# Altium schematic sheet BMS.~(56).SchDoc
size A3; SheetNumber: 8; SheetTotal: 14
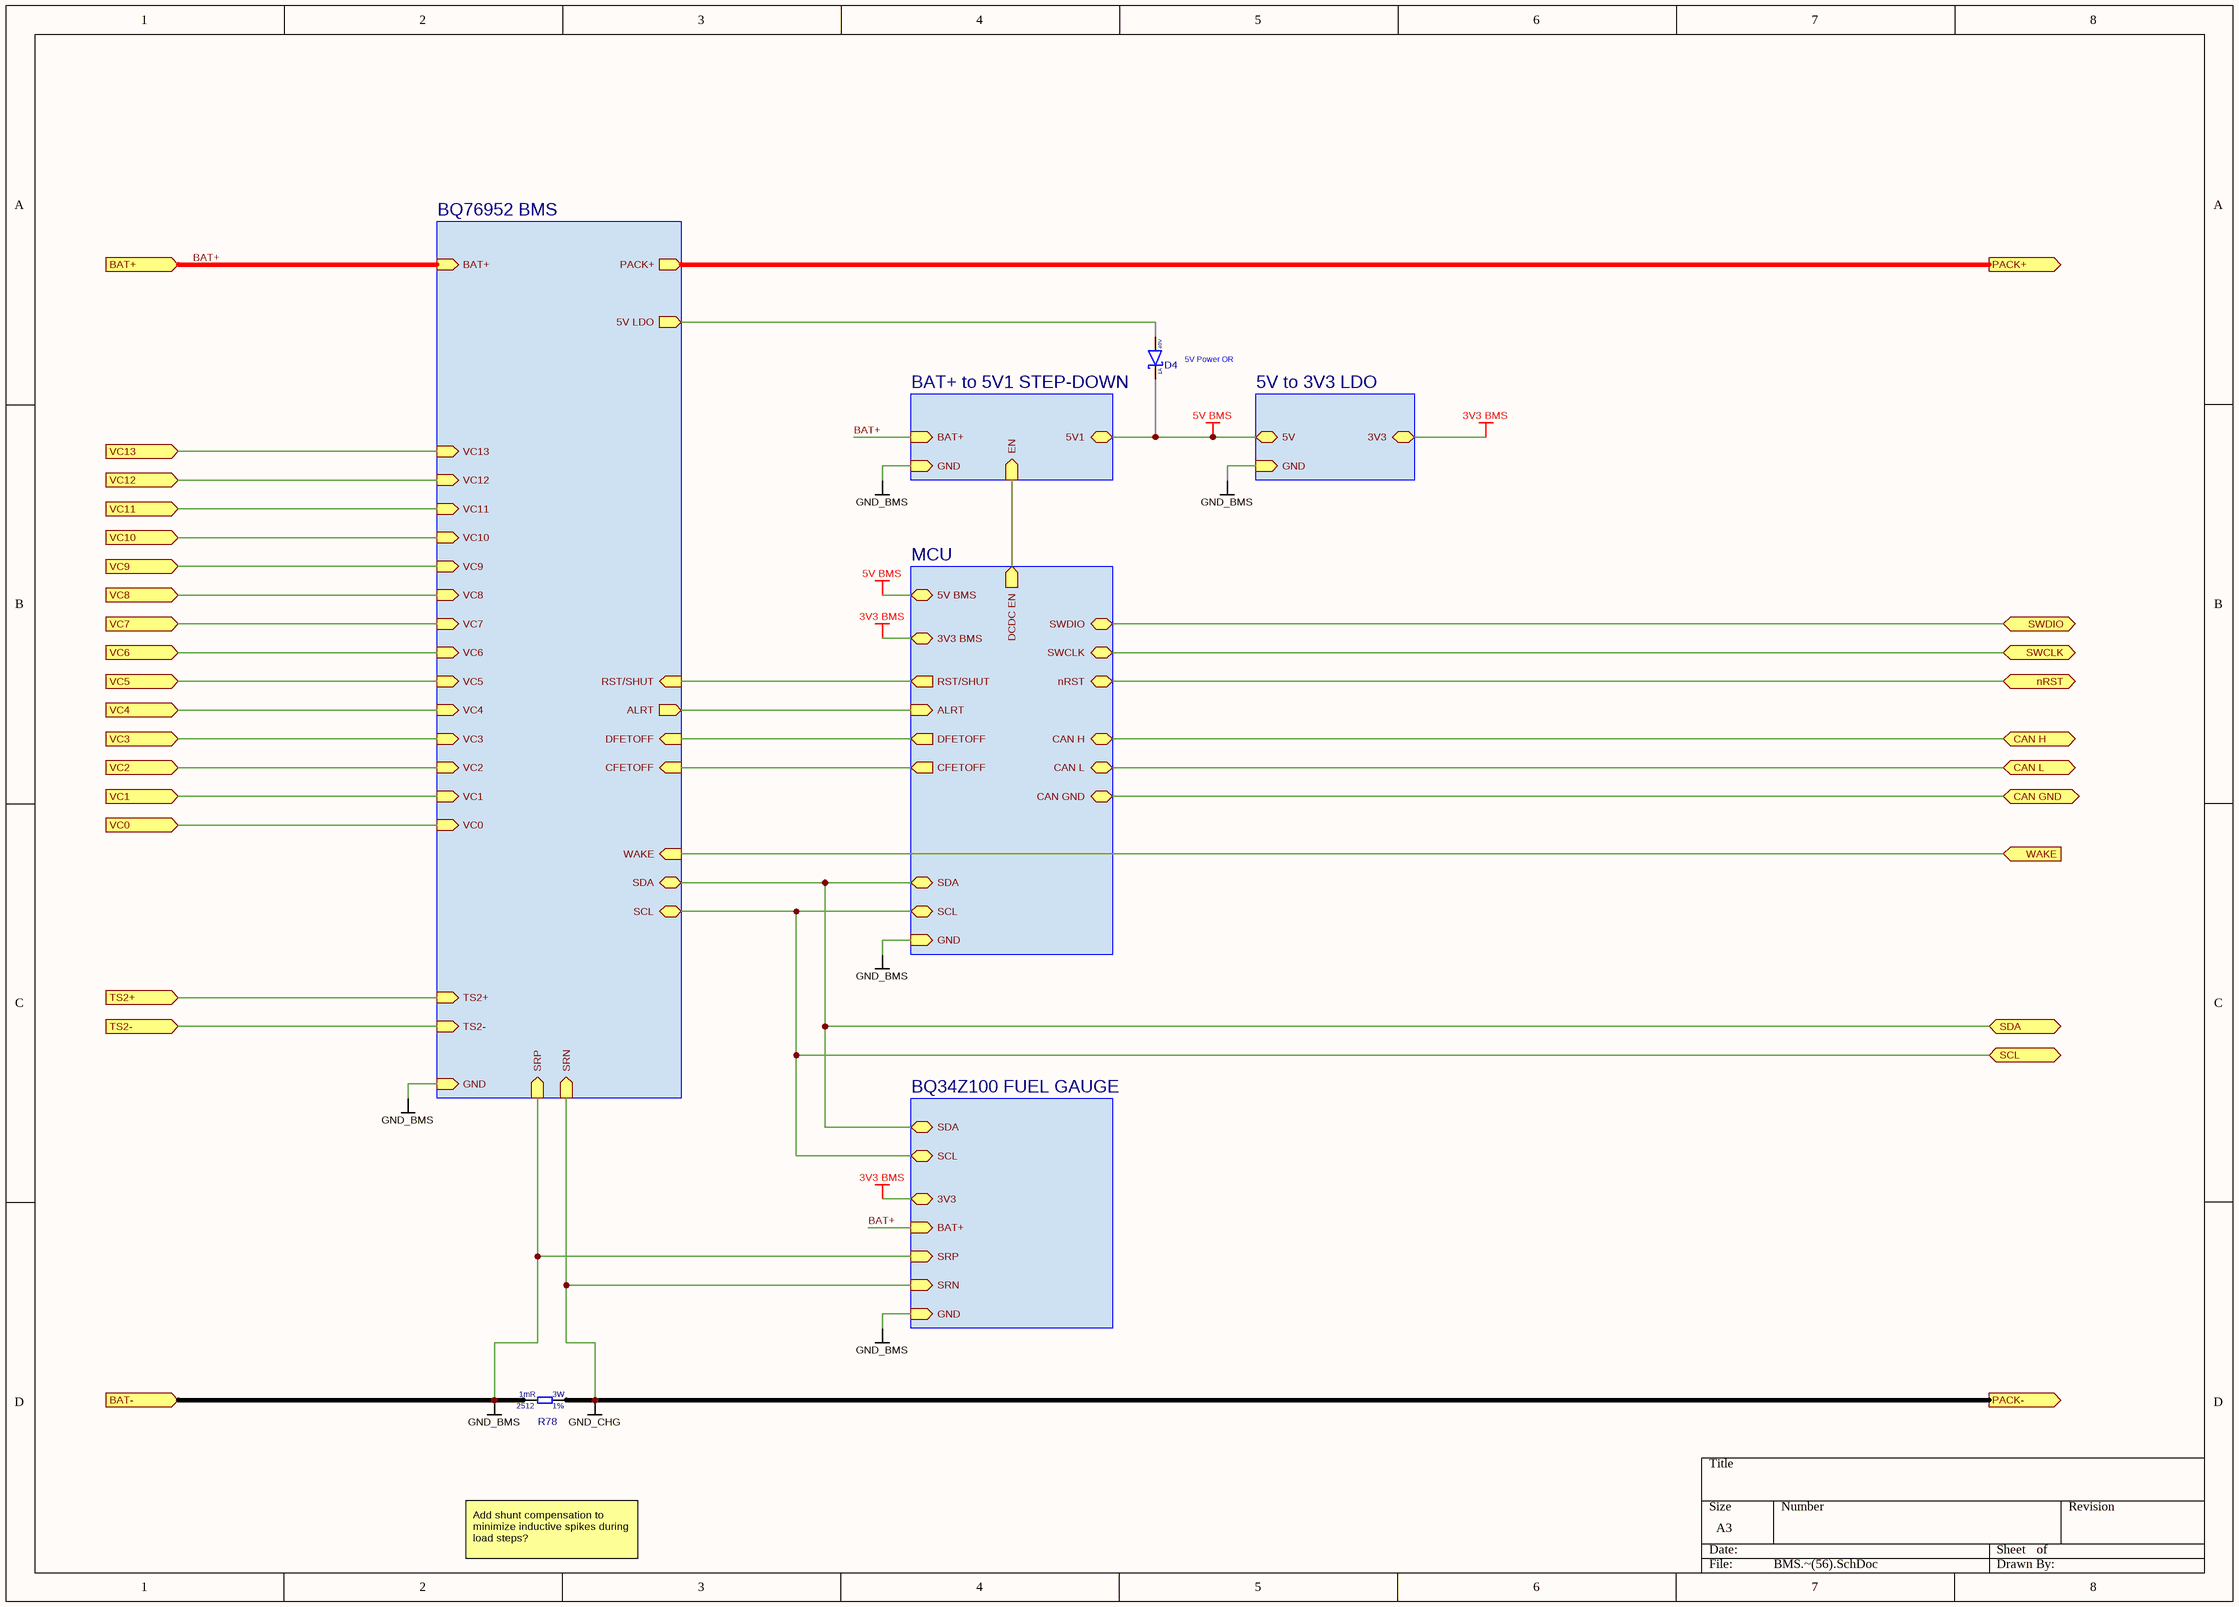
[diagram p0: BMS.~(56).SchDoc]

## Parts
D4  Forward Current: 1A  Reverse Voltage: 40V  [SOD-323]  (hidden comment: 1N5819WS)
R78  Resistance Tolerance: 1%  Resistance: 1mR  Power Rating: 3W  Case Code (Imperial): 2512  [2512 Shunt]  (hidden comment: HoYLR2512E-3W-1mR-1%)

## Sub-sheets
5V to 3V3 LDO = 5V to 3V3 LDO.SchDoc: 5V (bidir), 3V3 (bidir), GND (in)
BAT+ to 5V1 STEP-DOWN = BAT+ to 5V1 STEP-DOWN.SchDoc: 5V1 (bidir), BAT+ (in), EN (in), GND (in)
BQ34Z100 FUEL GAUGE = BQ34Z100 FUEL GAUGE.SchDoc: SRP (in), SRN (in), SDA (bidir), SCL (bidir), BAT+ (in), GND (in), 3V3 (bidir)
BQ76952 BMS = BQ76952 BMS.SchDoc: VC13 (in), VC12 (in), VC11 (in), VC10 (in), VC9 (in), VC8 (in), VC7 (in), VC6 (in), VC5 (in), VC4 (in), VC3 (in), VC2 (in), VC1 (in), VC0 (in), TS2+ (in), TS2- (in), BAT+ (in), PACK+ (out), 5V LDO (out), SRP (in), SRN (in), SDA (bidir), SCL (bidir), ALRT (out), DFETOFF (in), CFETOFF (in), RST/SHUT (in), WAKE (in), GND (in)
MCU = MCU.SchDoc: DCDC EN (out), 5V BMS (bidir), 3V3 BMS (bidir), SDA (bidir), SCL (bidir), ALRT (in), DFETOFF (out), CFETOFF (out), RST/SHUT (out), CAN H (bidir), CAN L (bidir), GND (in), nRST (bidir), SWCLK (bidir), SWDIO (bidir), CAN GND (bidir)

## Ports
BAT+ (in, see Arhitecture[3B], BAT+ to 5V1 STEP-DOWN[3B], BQ34Z100 FUEL GAUGE[3A], BQ76952 BMS[1A]), BAT- (in, see Arhitecture[3C]), CAN GND (bidir, see Arhitecture[4B], MCU[8B]), CAN H (bidir, see Arhitecture[4B], ESD system side[2B], MCU[8A]), CAN L (bidir, see Arhitecture[4B], ESD system side[2B], MCU[8B]), nRST (bidir, see Arhitecture[3C], MCU[8C]), PACK+ (out, see Arhitecture[4B], BQ76952 BMS[8A], Charger BQ25756[1A], CHARGER[1B], Power distribution[3A]), PACK- (out, see Arhitecture[4C], CHARGER[1C]), SCL (bidir, see Arhitecture[4C], BQ34Z100 FUEL GAUGE[5B], BQ76952 BMS[7C], MCU[1B]), SDA (bidir, see Arhitecture[4C], BQ34Z100 FUEL GAUGE[5B], BQ76952 BMS[7C], MCU[1B]), SWCLK (bidir, see Arhitecture[3C], MCU[8C]), SWDIO (bidir, see Arhitecture[3C], MCU[8C]), TS2+ (in, see Arhitecture[3C], BQ76952 BMS[3C]), TS2- (in, see Arhitecture[3C], BQ76952 BMS[3C]), VC0 (in, see Arhitecture[3B], BQ76952 BMS[1D]), VC1 (in, see Arhitecture[3B], BQ76952 BMS[1C]), VC2 (in, see Arhitecture[3B], BQ76952 BMS[1C]), VC3 (in, see Arhitecture[3B], BQ76952 BMS[1C]), VC4 (in, see Arhitecture[3B], BQ76952 BMS[1C]), VC5 (in, see Arhitecture[3B], BQ76952 BMS[1C]), VC6 (in, see Arhitecture[3B], BQ76952 BMS[1C]), VC7 (in, see Arhitecture[3B], BQ76952 BMS[1C]), VC8 (in, see Arhitecture[3B], BQ76952 BMS[1B]), VC9 (in, see Arhitecture[3B], BQ76952 BMS[1B]), VC10 (in, see Arhitecture[3B], BQ76952 BMS[1B]), VC11 (in, see Arhitecture[3B], BQ76952 BMS[1B]), VC12 (in, see Arhitecture[3B], BQ76952 BMS[1B]), VC13 (in, see Arhitecture[3B], BQ76952 BMS[1B]), WAKE (in, see Arhitecture[4B], BQ76952 BMS[3C])

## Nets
3V3 BMS: sheet BQ34Z100 FUEL GAUGE/3V3, sheet MCU/3V3 BMS, sheet 5V to 3V3 LDO/3V3
5V BMS: D4.K ; sheet MCU/5V BMS, sheet BAT+ to 5V1 STEP-DOWN/5V1, sheet 5V to 3V3 LDO/5V
GND_BMS: R78.1 ; port BAT-, sheet BQ76952 BMS/SRP, sheet BQ76952 BMS/GND, sheet BQ34Z100 FUEL GAUGE/SRP, sheet BQ34Z100 FUEL GAUGE/GND, sheet MCU/GND, sheet BAT+ to 5V1 STEP-DOWN/GND, sheet 5V to 3V3 LDO/GND
GND_CHG: R78.2 ; port PACK-, sheet BQ76952 BMS/SRN, sheet BQ34Z100 FUEL GAUGE/SRN
BAT+: port BAT+, sheet BQ76952 BMS/BAT+, sheet BQ34Z100 FUEL GAUGE/BAT+, sheet BAT+ to 5V1 STEP-DOWN/BAT+
CAN GND: port CAN GND, sheet MCU/CAN GND
CAN H: port CAN H, sheet MCU/CAN H
CAN L: port CAN L, sheet MCU/CAN L
nRST: port nRST, sheet MCU/nRST
PACK+: port PACK+, sheet BQ76952 BMS/PACK+
SCL: port SCL, sheet BQ76952 BMS/SCL, sheet BQ34Z100 FUEL GAUGE/SCL, sheet MCU/SCL
SDA: port SDA, sheet BQ76952 BMS/SDA, sheet BQ34Z100 FUEL GAUGE/SDA, sheet MCU/SDA
SWCLK: port SWCLK, sheet MCU/SWCLK
SWDIO: port SWDIO, sheet MCU/SWDIO
TS2+: port TS2+, sheet BQ76952 BMS/TS2+
TS2-: port TS2-, sheet BQ76952 BMS/TS2-
VC0: port VC0, sheet BQ76952 BMS/VC0
VC1: port VC1, sheet BQ76952 BMS/VC1
VC2: port VC2, sheet BQ76952 BMS/VC2
VC3: port VC3, sheet BQ76952 BMS/VC3
VC4: port VC4, sheet BQ76952 BMS/VC4
VC5: port VC5, sheet BQ76952 BMS/VC5
VC6: port VC6, sheet BQ76952 BMS/VC6
VC7: port VC7, sheet BQ76952 BMS/VC7
VC8: port VC8, sheet BQ76952 BMS/VC8
VC9: port VC9, sheet BQ76952 BMS/VC9
VC10: port VC10, sheet BQ76952 BMS/VC10
VC11: port VC11, sheet BQ76952 BMS/VC11
VC12: port VC12, sheet BQ76952 BMS/VC12
VC13: port VC13, sheet BQ76952 BMS/VC13
WAKE: port WAKE, sheet BQ76952 BMS/WAKE
NetD4_A: D4.A ; sheet BQ76952 BMS/5V LDO
(unnamed): sheet BQ76952 BMS/ALRT, sheet MCU/ALRT
(unnamed): sheet BQ76952 BMS/DFETOFF, sheet MCU/DFETOFF  [a separate net that carries the same name]
(unnamed): sheet BQ76952 BMS/CFETOFF, sheet MCU/CFETOFF  [a separate net that carries the same name]
(unnamed): sheet BQ76952 BMS/RST/SHUT, sheet MCU/RST/SHUT  [a separate net that carries the same name]
(unnamed): sheet MCU/DCDC EN, sheet BAT+ to 5V1 STEP-DOWN/EN  [a separate net that carries the same name]

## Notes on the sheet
- (near D4) 5V Power OR
- Add shunt compensation to minimize inductive spikes during load steps?

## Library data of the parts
D4 = 1N5819WS: Schottky 40V 1A 600mVf SOD-323; Manufacturer: Guangdong Hottech
R78 = HoYLR2512E-3W-1mR-1%: RES 1mR 2512 3W 1%; Manufacturer: Miliohm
